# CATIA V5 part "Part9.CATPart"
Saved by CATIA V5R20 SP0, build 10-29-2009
Part number: 3JT12.5X2.5X17.5
Revision: ANY
Definition: UNKNOWN
Nomenclature: 3JT12.5X2.5X17.5
Source: Unknown
Bounding box of the stored display mesh (mm): x -8.75 to 8.75, y -1.25 to 1.25, z -8.75 to 8.75
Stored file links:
  C:\Users\Utente\Desktop\IO LAVORO\3D X SITO CF\CUMSA\3D files PW\pw101430\pw101430_injection\Part9.CATPart
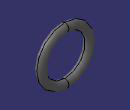
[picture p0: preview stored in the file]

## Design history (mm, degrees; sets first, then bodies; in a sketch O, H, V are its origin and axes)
Body1 "Revolución1" (main body)
  Solid1: solid without history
